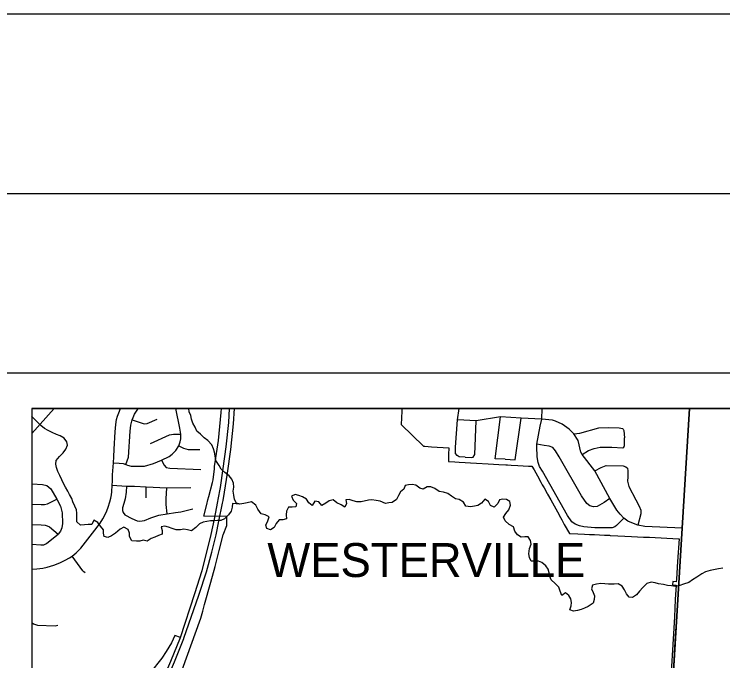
# Model space of a CAD drawing. Extents: x 0 to 34, y 0 to 22.
# Drawn here: x 2.051 to 4.027, y 20.197 to 22 of the extents above; entities that cross this region are included whole.
import ezdxf

# ---------------------------------------------------------------- set-up
doc = ezdxf.new("R2010")
doc.units = 0
for name, color, linetype in [('GM_X_City_Street', 7, 'Continuous'), ('GM_X_Corporation', 7, 'Continuous'), ('GM_X_Corporation_Text', 7, 'Continuous'), ('GM_X_County_Road', 7, 'Continuous'), ('GM_X_Interchange_Ramps', 7, 'Continuous'), ('GM_X_Interstate_Route', 7, 'Continuous'), ('GM_X_Minor_River', 7, 'Continuous'), ('SH_Border', 7, 'Continuous'), ('SH_Cut_Line', 7, 'Continuous'), ('SH_Data', 7, 'Continuous')]:
    doc.layers.add(name, color=color, linetype=linetype)

msp = doc.modelspace()

# ---------------------------------------------------------------- linework, layer by layer
at = {"layer": 'GM_X_City_Street'}
for p, q in [((2.1, 20.8307), (2.1618, 20.9)), ((2.1005, 20.6899), (2.101, 20.7188)), ((2.4183, 20.651), (2.4187, 20.6822))]:
    msp.add_line(p, q, dxfattribs=at)
for points in [[(2.3271, 20.7492), (2.3437, 20.7482), (2.354, 20.7466), (2.3619, 20.7444), (2.367, 20.7418), (2.3766, 20.7393), (2.3955, 20.7391), (2.4144, 20.7397), (2.4394, 20.7473), (2.4611, 20.7564), (2.4832, 20.7666), (2.4915, 20.7727), (2.5014, 20.7827), (2.5094, 20.7964), (2.5136, 20.8073), (2.515, 20.8157), (2.5154, 20.829), (2.5126, 20.8458), (2.5014, 20.9)], [(2.3271, 20.7492), (2.3281, 20.7656), (2.3294, 20.787), (2.332, 20.8348), (2.3336, 20.8559), (2.3361, 20.8695), (2.3387, 20.8791), (2.3422, 20.8884), (2.3472, 20.9)], [(2.3619, 20.7444), (2.366, 20.7543), (2.3695, 20.765), (2.3738, 20.8373), (2.3757, 20.8536), (2.3798, 20.8685), (2.3823, 20.8751), (2.3864, 20.8845), (2.3953, 20.8986), (2.3967, 20.9)], [(3.3079, 20.7641), (3.2917, 20.7657), (3.2856, 20.7695), (3.2815, 20.7745), (3.2812, 20.7923), (3.2864, 20.8686), (3.2914, 20.9)], [(3.5178, 20.851), (3.5217, 20.8709), (3.5232, 20.9)], [(2.3798, 20.8685), (2.4132, 20.8572), (2.4215, 20.8588), (2.4489, 20.8709)], [(3.7118, 20.6496), (3.6701, 20.7265), (3.6347, 20.7724), (3.6311, 20.7786), (3.6231, 20.8107), (3.6116, 20.8296), (3.5983, 20.8425), (3.5787, 20.8569), (3.5605, 20.8649), (3.5514, 20.8674), (3.5217, 20.8709), (3.4644, 20.8737), (3.407, 20.8772), (3.3387, 20.8661), (3.2864, 20.8686)], [(3.4201, 20.759), (3.3916, 20.7599), (3.407, 20.8772)], [(3.4201, 20.759), (3.4481, 20.757), (3.4644, 20.8737)], [(3.3079, 20.7641), (3.3261, 20.764), (3.3307, 20.7648), (3.3352, 20.7716), (3.3387, 20.8661)], [(3.7511, 20.5949), (3.7303, 20.5743), (3.7254, 20.5706), (3.7178, 20.5679), (3.6697, 20.5674), (3.6394, 20.5702), (3.6269, 20.5729), (3.6148, 20.5779), (3.6057, 20.584), (3.5937, 20.6015), (3.5237, 20.7256), (3.5158, 20.7381), (3.5121, 20.7499), (3.5087, 20.7655), (3.5077, 20.7939), (3.5081, 20.8012), (3.5178, 20.851)], [(3.6116, 20.8296), (3.6279, 20.8314), (3.6807, 20.8467), (3.7083, 20.8477), (3.7375, 20.8464), (3.747, 20.8449), (3.7492, 20.8426), (3.7507, 20.8388), (3.7529, 20.8183)], [(2.4309, 20.803), (2.4835, 20.8265), (2.4951, 20.8286), (2.5154, 20.829)], [(3.6347, 20.7724), (3.6524, 20.7827), (3.6683, 20.7891), (3.685, 20.7924), (3.7168, 20.7926), (3.7482, 20.7902), (3.7509, 20.7921), (3.7524, 20.797), (3.7529, 20.8183)], [(2.5094, 20.7964), (2.5227, 20.7894), (2.5361, 20.7862), (2.5683, 20.7855)], [(3.7118, 20.6496), (3.6961, 20.6383), (3.676, 20.6266), (3.6658, 20.6259), (3.6563, 20.6286), (3.6472, 20.6354), (3.6322, 20.6571), (3.5701, 20.7656), (3.5603, 20.7819), (3.5528, 20.7915), (3.5429, 20.7957), (3.5289, 20.7969), (3.5081, 20.8012)], [(2.4611, 20.7564), (2.4691, 20.7421), (2.4747, 20.7361), (2.4849, 20.7337), (2.5715, 20.7302)], [(2.1, 20.4519), (2.114, 20.4528), (2.1304, 20.4549), (2.1429, 20.4577), (2.1609, 20.4631), (2.1783, 20.4702), (2.1923, 20.4771), (2.2048, 20.484), (2.2118, 20.4886), (2.2235, 20.498), (2.2301, 20.5041), (2.2367, 20.5111), (2.2752, 20.5612), (2.2899, 20.5803), (2.2976, 20.5922), (2.3036, 20.6032), (2.3086, 20.6146), (2.3129, 20.6251), (2.3177, 20.6397), (2.3205, 20.6501), (2.322, 20.6591), (2.323, 20.6683), (2.3238, 20.6863), (2.3243, 20.6977), (2.3249, 20.7156), (2.3271, 20.7492)], [(3.6701, 20.7265), (3.6874, 20.7355), (3.701, 20.7415), (3.7487, 20.7401), (3.7564, 20.738), (3.7609, 20.7342), (3.762, 20.7268), (3.7616, 20.7093), (3.7606, 20.6973), (3.7648, 20.6826), (3.7841, 20.6454), (3.7939, 20.6275), (3.7978, 20.617), (3.7978, 20.6068), (3.7894, 20.5753)], [(2.1, 20.6899), (2.1005, 20.6899), (2.1293, 20.6885), (2.1415, 20.6853), (2.1531, 20.6759), (2.1696, 20.6475), (2.1797, 20.6282), (2.1846, 20.6093), (2.1855, 20.5798), (2.1834, 20.5679), (2.1797, 20.5586), (2.1734, 20.5501)], [(2.3238, 20.6863), (2.3634, 20.6841), (2.3856, 20.6834), (2.4187, 20.6822), (2.4761, 20.679), (2.5436, 20.6798)], [(2.3634, 20.6841), (2.3626, 20.6672), (2.3603, 20.6487), (2.3563, 20.6353), (2.353, 20.6231), (2.3526, 20.6192), (2.3527, 20.6154), (2.3545, 20.6098), (2.3588, 20.6039), (2.3787, 20.5935), (2.3931, 20.5872), (2.4012, 20.5858), (2.4138, 20.5883), (2.4316, 20.5956), (2.4541, 20.603), (2.4772, 20.6065), (2.5, 20.6103), (2.5157, 20.6117), (2.5483, 20.6205)], [(2.4772, 20.6065), (2.4744, 20.6321), (2.4747, 20.6482), (2.4761, 20.679)], [(2.1, 20.6336), (2.1254, 20.6322), (2.1354, 20.6326), (2.1435, 20.6347), (2.1513, 20.6378), (2.1696, 20.6475)], [(3.9132, 20.5665), (3.809, 20.5714), (3.7894, 20.5753), (3.7729, 20.5812), (3.7623, 20.5865), (3.7511, 20.5949), (3.7409, 20.6058), (3.7315, 20.617), (3.7118, 20.6496)], [(2.1, 20.5769), (2.1256, 20.5756), (2.1371, 20.5749), (2.1424, 20.5735), (2.1487, 20.5704), (2.1734, 20.5501)], [(2.1, 20.5217), (2.1249, 20.5205), (2.1331, 20.5201), (2.141, 20.5238), (2.151, 20.5317), (2.1734, 20.5501)], [(2.2483, 20.4418), (2.2449, 20.4447), (2.2419, 20.4477), (2.2118, 20.4886)], [(2.1, 20.3032), (2.104, 20.3002), (2.1156, 20.2964), (2.165, 20.2946), (2.172, 20.2964)]]:
    msp.add_lwpolyline(points, dxfattribs=at)
at = {"layer": 'GM_X_Corporation'}
for points in [[(2.5189, 20.1714), (2.571, 20.3158), (2.5762, 20.3349), (2.5813, 20.3533), (2.5988, 20.4163), (2.6112, 20.46), (2.6226, 20.504), (2.6329, 20.5483), (2.6434, 20.5743), (2.6434, 20.5896), (2.6435, 20.5993), (2.5795, 20.5996), (2.5876, 20.6329), (2.5906, 20.6452), (2.593, 20.6546), (2.6032, 20.6943), (2.6051, 20.7016), (2.6088, 20.7324), (2.6095, 20.7381), (2.6119, 20.7563), (2.6145, 20.7745), (2.6201, 20.8109), (2.6241, 20.8498), (2.6275, 20.8889), (2.6283, 20.9), (2.1, 20.9), (2.1, 14.1)], [(7.1445, 20.9), (3.132, 20.9), (3.1316, 20.8932), (3.1295, 20.8556), (3.1923, 20.795), (3.1957, 20.7948), (3.2147, 20.7936), (3.2622, 20.7906), (3.2618, 20.7716), (3.2614, 20.7527), (3.2794, 20.7517), (3.2911, 20.751), (3.3085, 20.7499), (3.323, 20.7491), (3.3394, 20.7481), (3.3721, 20.7462), (3.4022, 20.7444), (3.4212, 20.7432), (3.4262, 20.7429), (3.4363, 20.7424), (3.455, 20.7414), (3.485, 20.7399), (3.4945, 20.7394), (3.5003, 20.7288), (3.5096, 20.7122), (3.5192, 20.6949), (3.5232, 20.6877), (3.5283, 20.6786), (3.5371, 20.6628), (3.5381, 20.6611), (3.5468, 20.6454), (3.556, 20.6288), (3.5653, 20.6122), (3.5744, 20.5959), (3.5778, 20.5896), (3.5847, 20.5772), (3.5988, 20.552), (3.6225, 20.5509), (3.6413, 20.55), (3.6549, 20.5493), (3.6693, 20.5486), (3.683, 20.5479), (3.6971, 20.5472), (3.7109, 20.5466), (3.713, 20.5465), (3.734, 20.5454), (3.7538, 20.5445), (3.7724, 20.5436), (3.7892, 20.5427), (3.8056, 20.5419), (3.8221, 20.5411), (3.9029, 20.5372), (3.9047, 20.5371), (3.9005, 20.4735), (3.8974, 20.4245), (3.897, 20.4172), (3.8874, 20.4178), (3.8867, 20.4083), (3.8964, 20.4077), (3.8943, 20.3676), (3.8919, 20.3191), (3.89, 20.2875), (3.8798, 20.1203)]]:
    msp.add_lwpolyline(points, dxfattribs=at)
at = {"layer": 'GM_X_County_Road'}
for p, q in [((3.8952, 20.2667), (3.8982, 20.3166)), ((3.8892, 20.1667), (3.8952, 20.2667))]:
    msp.add_line(p, q, dxfattribs=at)
for points in [[(3.8752, 19.9374), (3.913, 20.567), (3.9336, 20.9), (2.1, 20.9), (2.1, 16.5143)], [(8.6772, 20.9), (3.9336, 20.9), (3.913, 20.567), (3.8752, 19.9374)], [(3.8982, 20.3166), (3.9132, 20.5665), (3.9338, 20.9)]]:
    msp.add_lwpolyline(points, dxfattribs=at)
at = {"layer": 'GM_X_Interchange_Ramps'}
msp.add_lwpolyline([(2.5142, 20.2619), (2.499, 20.2676), (2.4895, 20.2472), (2.4746, 20.2222), (2.4623, 20.2043), (2.4507, 20.1897), (2.4408, 20.1771), (2.4292, 20.1634), (2.4158, 20.15), (2.4044, 20.1389), (2.3901, 20.127), (2.3752, 20.1145), (2.3477, 20.0951), (2.3119, 20.07)], dxfattribs=at)
at = {"layer": 'GM_X_Interstate_Route'}
for points in [[(2.6196, 20.6468), (2.6256, 20.68), (2.6337, 20.7327), (2.6416, 20.793), (2.649, 20.8612), (2.6514, 20.9)], [(2.6331, 20.6441), (2.6368, 20.6666), (2.6456, 20.7197), (2.6546, 20.7864), (2.662, 20.8577), (2.6649, 20.9)], [(2.1, 19.441), (2.1547, 19.5462), (2.177, 19.5875), (2.1804, 19.5939), (2.2126, 19.6548), (2.2316, 19.6901), (2.266, 19.7543), (2.3324, 19.8769), (2.3576, 19.9259), (2.3645, 19.9387), (2.3749, 19.9579), (2.4137, 20.0313), (2.4306, 20.0664), (2.4549, 20.1204), (2.4876, 20.1956), (2.5142, 20.2619), (2.5547, 20.3839), (2.5745, 20.4486), (2.5887, 20.5033), (2.5997, 20.5493), (2.6091, 20.5921), (2.6185, 20.641), (2.6196, 20.6468)], [(2.5664, 20.3822), (2.5869, 20.4448), (2.6016, 20.4996), (2.6134, 20.5483), (2.6213, 20.5863), (2.6319, 20.6362), (2.6331, 20.6441)], [(2.5236, 20.2594), (2.5655, 20.3794), (2.5664, 20.3822)], [(2.3651, 19.918), (2.3688, 19.9251), (2.3757, 19.938), (2.384, 19.9535), (2.4234, 20.0269), (2.4408, 20.0616), (2.4641, 20.1161), (2.498, 20.1942), (2.5233, 20.2584), (2.5236, 20.2594)]]:
    msp.add_lwpolyline(points, dxfattribs=at)
at = {"layer": 'GM_X_Minor_River'}
for points in [[(2.6801, 20.6336), (2.6702, 20.6363), (2.6646, 20.6463), (2.6629, 20.6588), (2.6614, 20.6698), (2.6631, 20.6805), (2.6624, 20.6922), (2.6572, 20.7029), (2.6497, 20.7125), (2.638, 20.7221), (2.6275, 20.7309), (2.6219, 20.7412), (2.6133, 20.7553), (2.6112, 20.7683), (2.609, 20.7785), (2.606, 20.7881), (2.6016, 20.7987), (2.5907, 20.8106), (2.5802, 20.8187), (2.57, 20.8283), (2.5602, 20.8375), (2.555, 20.8485), (2.5491, 20.8592), (2.5446, 20.8703), (2.5428, 20.8805), (2.5387, 20.8908), (2.5374, 20.9)], [(2.6801, 20.6336), (2.6592, 20.6353), (2.6584, 20.6247), (2.656, 20.6137), (2.648, 20.6039), (2.6373, 20.593), (2.627, 20.5881), (2.6175, 20.5875), (2.608, 20.5872), (2.5982, 20.5869), (2.5875, 20.5851), (2.5777, 20.5837), (2.5674, 20.5784), (2.5567, 20.5683), (2.5452, 20.5593), (2.5339, 20.5617), (2.5237, 20.5637), (2.5142, 20.5618), (2.5024, 20.562), (2.4915, 20.5659), (2.4809, 20.5694), (2.4703, 20.5721), (2.4604, 20.5707), (2.463, 20.5597), (2.4633, 20.5498), (2.453, 20.5461), (2.4431, 20.5416), (2.4325, 20.5379), (2.4214, 20.5301), (2.4104, 20.5328), (2.4009, 20.5299), (2.3915, 20.5303), (2.379, 20.5312), (2.3723, 20.5434), (2.3723, 20.5529), (2.3686, 20.5632), (2.3566, 20.569), (2.3459, 20.5642), (2.3329, 20.5525), (2.3219, 20.545), (2.3116, 20.5402), (2.3014, 20.543), (2.3, 20.5528), (2.2997, 20.5623), (2.2914, 20.5723), (2.2835, 20.5822), (2.273, 20.5888), (2.2668, 20.5771), (2.257, 20.5772), (2.2463, 20.5757), (2.2357, 20.5747), (2.2248, 20.5843), (2.2249, 20.5976), (2.2254, 20.6082), (2.2244, 20.6177), (2.2195, 20.628), (2.2143, 20.6398), (2.2114, 20.6497), (2.2047, 20.6604), (2.2002, 20.67), (2.1938, 20.681), (2.1879, 20.6913), (2.183, 20.7013), (2.1778, 20.7135), (2.1723, 20.7249), (2.1689, 20.7356), (2.1668, 20.7451), (2.168, 20.7553), (2.1772, 20.7662), (2.1871, 20.7768), (2.1944, 20.7866), (2.1991, 20.7976), (2.1969, 20.8074), (2.1901, 20.8174), (2.1792, 20.8243), (2.1683, 20.8278), (2.1566, 20.8333), (2.1456, 20.8387), (2.1354, 20.8449), (2.1249, 20.8525), (2.1136, 20.8644), (2.1027, 20.8755), (2.1, 20.8788)], [(3.4902, 20.5326), (3.4839, 20.5421), (3.4744, 20.5426), (3.4646, 20.5416), (3.454, 20.5477), (3.4465, 20.5581), (3.4428, 20.5699), (3.4311, 20.5772), (3.4199, 20.5872), (3.4154, 20.5971), (3.4212, 20.6073), (3.43, 20.6178), (3.4347, 20.6303), (3.4332, 20.6406), (3.4234, 20.6464), (3.4136, 20.6476), (3.4037, 20.6454), (3.3995, 20.6352), (3.3891, 20.6251), (3.3786, 20.6297), (3.3733, 20.6408), (3.3628, 20.6477), (3.354, 20.636), (3.3437, 20.6297), (3.3342, 20.6275), (3.3232, 20.6261), (3.3103, 20.6277), (3.3036, 20.6395), (3.2919, 20.6465), (3.2813, 20.6488), (3.27, 20.6554), (3.2595, 20.6631), (3.2474, 20.667), (3.2353, 20.669), (3.2236, 20.6775), (3.2123, 20.6818), (3.202, 20.6815), (3.1914, 20.6755), (3.1815, 20.6783), (3.171, 20.6867), (3.16, 20.688), (3.1505, 20.6877), (3.141, 20.6859), (3.1372, 20.6756), (3.1276, 20.6678), (3.1222, 20.6579), (3.1164, 20.6466), (3.105, 20.6383), (3.0955, 20.6373), (3.0856, 20.6355), (3.0709, 20.6417), (3.0599, 20.6437), (3.0478, 20.6453), (3.0383, 20.6447), (3.0178, 20.6403), (3.0065, 20.64), (2.9955, 20.6432), (2.9849, 20.6467), (2.9754, 20.6453), (2.9776, 20.635), (2.973, 20.6248), (2.962, 20.6317), (2.9507, 20.6375), (2.9398, 20.646), (2.9292, 20.6427), (2.9193, 20.6359), (2.9086, 20.6299), (2.9, 20.6403), (2.8886, 20.6415), (2.8817, 20.6302), (2.8719, 20.6371), (2.8659, 20.6474), (2.855, 20.654), (2.8444, 20.6579), (2.8338, 20.6606), (2.8235, 20.6554), (2.8284, 20.6451), (2.8378, 20.6352), (2.8362, 20.6257), (2.8255, 20.625), (2.8157, 20.6247), (2.8099, 20.6138), (2.809, 20.6039), (2.8097, 20.5929), (2.7994, 20.5896), (2.7896, 20.5897), (2.7808, 20.5799), (2.7758, 20.5681), (2.7651, 20.5618), (2.7549, 20.5653), (2.7527, 20.5752), (2.7581, 20.5873), (2.762, 20.5979), (2.7507, 20.6037), (2.739, 20.6068), (2.7296, 20.6198), (2.7244, 20.6309), (2.712, 20.6397), (2.7002, 20.6372), (2.6907, 20.6354), (2.6801, 20.6336)], [(4.0269, 20.4546), (4.0148, 20.4532), (4.0053, 20.4514), (3.9913, 20.4485), (3.9784, 20.4452), (3.9684, 20.4396), (3.9543, 20.4302), (3.9418, 20.422), (3.9322, 20.4152), (3.9174, 20.4108), (3.9068, 20.4071), (3.8935, 20.4038), (3.8833, 20.4055), (3.8727, 20.4067), (3.8613, 20.4091), (3.8477, 20.4115), (3.8378, 20.4139), (3.8269, 20.4155), (3.8147, 20.4118), (3.804, 20.4009), (3.7948, 20.3907), (3.786, 20.3809), (3.7753, 20.3734), (3.7659, 20.3739), (3.758, 20.3835), (3.7524, 20.3946), (3.7461, 20.4049), (3.7351, 20.4114), (3.7241, 20.4104), (3.7082, 20.4102), (3.698, 20.411), (3.6862, 20.4126), (3.6741, 20.4101), (3.6631, 20.4079), (3.6603, 20.3973), (3.6648, 20.387), (3.6692, 20.3775), (3.6676, 20.3673), (3.6649, 20.357), (3.6516, 20.348), (3.6413, 20.3436), (3.6314, 20.3395), (3.6215, 20.3366), (3.6101, 20.3348), (3.6003, 20.3387), (3.6042, 20.3496), (3.6047, 20.3595), (3.6029, 20.3694), (3.5976, 20.3789), (3.5878, 20.3859), (3.5775, 20.3791), (3.5731, 20.3909), (3.569, 20.402), (3.5589, 20.4123), (3.548, 20.4227), (3.5447, 20.4322), (3.5421, 20.4421), (3.5395, 20.452), (3.5332, 20.4619), (3.5223, 20.4708), (3.5125, 20.4743), (3.5018, 20.4744), (3.492, 20.4749), (3.4875, 20.4848), (3.4861, 20.495), (3.4878, 20.5095), (3.492, 20.5216), (3.4902, 20.5326)]]:
    msp.add_lwpolyline(points, dxfattribs=at)
at = {"layer": 'SH_Border'}
msp.add_lwpolyline([(1.5, 21.5), (33.5, 21.5), (33.5, 0.5), (1.5, 0.5)], close=True, dxfattribs=at)
at = {"layer": 'SH_Cut_Line'}
msp.add_lwpolyline([(0, 0), (34, 0), (34, 22), (0, 22)], close=True, dxfattribs=at)
at = {"layer": 'SH_Data'}
for p, q in [((2, 21), (9, 21)), ((2.1, 20.9), (2.1, 14.1)), ((2.1, 20.9), (8.9, 20.9))]:
    msp.add_line(p, q, dxfattribs=at)

# ---------------------------------------------------------------- texts
at = {"layer": 'GM_X_Corporation_Text'}
msp.add_text('WESTERVILLE', height=0.094697, rotation=0, dxfattribs=at).set_placement((2.7566, 20.4303))

doc.saveas('drawing.dxf')
